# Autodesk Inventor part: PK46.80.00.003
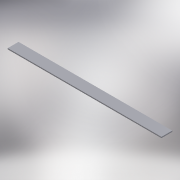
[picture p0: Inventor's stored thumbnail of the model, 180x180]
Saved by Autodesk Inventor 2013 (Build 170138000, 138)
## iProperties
Shininess: 64.0
Length Units: 11269
Angle Units: 11279
Time Units: 11290
Mass Units: 11283
Length Display Precision: 3
Angle Display Precision: 2
Compacted: True
Part Number: PK46.80.00.003
Document SubType Name: Modeling
Created: 2005-01
Material: Steel, Mild
Designer: SAlex
Manufacturer: Standard
Standards Organization: Custom
Density: 7.86 g/cm^3
Mass: 11161.2 g
Surface Area: 3144 cm^2
Volume: 1420 cm^3
Density: 0.0
Volumn: 0.0
Area: 0.0
PropertySet Name: Model Information
Control State: 0
Master: False
Checked Out: False
Checked Out Date: 2008-10-15
Last Check In Date: 2008-10-15
Author: SAlex
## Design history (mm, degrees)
sketch "Sketch1"
  geometry: L1 (0, 0)-(1420, 0); L2 (1420, 0)-(1420, 100); L3 (1420, 100)-(0, 100); L4 (0, 100)-(0, 0)
  constraints: 8 end point, 2 parallel, 1 horizontal, 1 perpendicular, 1 other
  dimensions: "d0" = 100 distance of L3.end L1.start; "d1" = 1420 distance of L2.end L3.end
extrude "Extrusion1" new body sketch "Sketch1" distance "d2" = 10; taper "d3" = 0 deg
body "Solid1"
